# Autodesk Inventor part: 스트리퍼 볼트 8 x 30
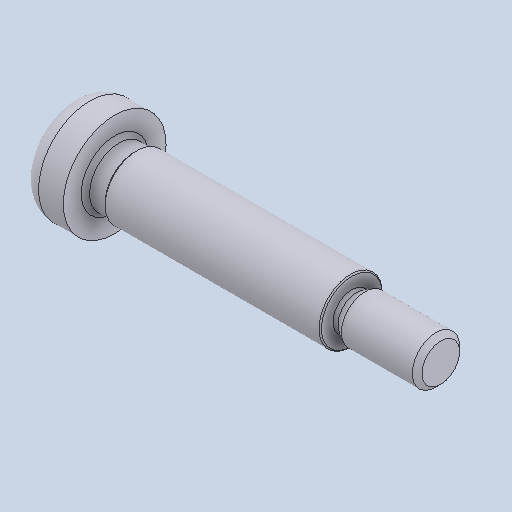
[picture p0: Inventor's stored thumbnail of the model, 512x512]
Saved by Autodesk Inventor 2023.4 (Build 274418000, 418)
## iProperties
Created: 2024-04
Part Number: 스트리퍼 볼트 8 x 30
Material: 강철, 연강
Description: 6각 소켓 머리 숄더 나사
Document SubType Name: Modeling
Designer: EDU
Density: 7.86 g/cm^3
Appearance: 기본값
Author: jhkim
Sending System: Autodesk Inventor 2025
Preprocessor: ST-DEVELOPER v20
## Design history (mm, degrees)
node "스트리퍼 볼트 8 x 301"
node "솔리드1"
body "Solid1"
